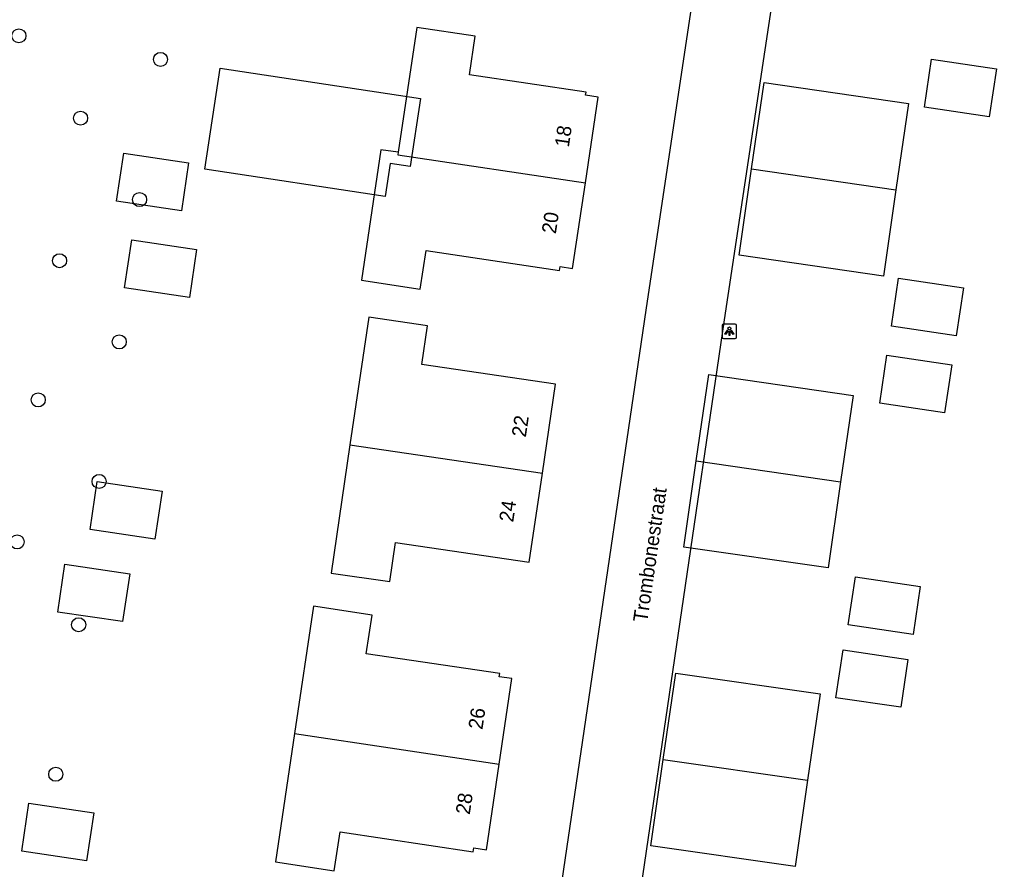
# Model space of a CAD drawing. Extents: x 164150 to 165261, y 382513 to 383432.
# Drawn here: x 164601.9 to 164669.9, y 382912.1 to 382971.2 of the extents above; entities that cross this region are included whole.
import ezdxf

# ---------------------------------------------------------------- set-up
doc = ezdxf.new("R2010")
doc.units = 0
for name, color, linetype in [('IMGEO_Boom', 7, 'Continuous'), ('IMGEO_Lichtpunt', 7, 'Continuous'), ('IMGEO_Openbare_ruimte_label', 7, 'Continuous'), ('IMGEO_Pand', 7, 'Continuous'), ('IMGEO_Pand_nummerreeks', 7, 'Continuous'), ('IMGEO_Pand_vergunning_verleend', 7, 'Continuous'), ('IMGEO_Rijbaan_lokaal_gesloten', 7, 'Continuous')]:
    doc.layers.add(name, color=color, linetype=linetype)

msp = doc.modelspace()

# ---------------------------------------------------------------- linework, layer by layer
at = {"layer": 'IMGEO_Boom'}
for centre in [(164601.874, 382970.068), (164611.726, 382968.429), (164606.168, 382964.34), (164610.269, 382958.67), (164604.702, 382954.42), (164608.857, 382948.767), (164603.219, 382944.734), (164607.456, 382939.06), (164601.753, 382934.851), (164606.031, 382929.089), (164604.437, 382918.68)]:
    msp.add_circle(centre, 0.489, dxfattribs=at)
at = {"layer": 'IMGEO_Lichtpunt'}
for p, q in [((164650.795, 382949.911), (164650.795, 382949.104)), ((164650.795, 382949.911), (164650.795, 382949.104)), ((164651.697, 382950.006), (164650.889, 382950.006)), ((164651.697, 382950.006), (164650.889, 382950.006)), ((164651.791, 382949.104), (164651.791, 382949.911)), ((164651.791, 382949.104), (164651.791, 382949.911)), ((164650.889, 382949.01), (164651.697, 382949.01)), ((164650.889, 382949.01), (164651.697, 382949.01))]:
    msp.add_line(p, q, dxfattribs=at)
for points in [[(164651.169, 382949.575), (164651.208, 382949.547), (164651.02, 382949.285), (164650.982, 382949.312), (164651.169, 382949.575)], [(164651.271, 382949.527), (164651.318, 382949.527), (164651.318, 382949.205), (164651.271, 382949.205), (164651.271, 382949.527)], [(164651.381, 382949.547), (164651.419, 382949.574), (164651.606, 382949.312), (164651.567, 382949.284), (164651.381, 382949.547)]]:
    msp.add_lwpolyline(points, dxfattribs=at)
msp.add_circle((164651.294, 382949.709), 0.0994, dxfattribs=at)
for centre, start, end in [((164650.889, 382949.911), 90, 180), ((164650.889, 382949.911), 90, 180), ((164651.697, 382949.911), 0, 90), ((164651.697, 382949.911), 0, 90), ((164650.889, 382949.104), 180, 270), ((164650.889, 382949.104), 180, 270), ((164651.697, 382949.104), 270, 0), ((164651.697, 382949.104), 270, 360)]:
    msp.add_arc(centre, 0.0946, start, end, dxfattribs=at)
at = {"layer": 'IMGEO_Pand'}
for points in [[(164641.274, 382959.842), (164642.165, 382965.796), (164641.296, 382965.936), (164641.329, 382966.158), (164633.225, 382967.358), (164633.618, 382970.037), (164629.544, 382970.648), (164628.257, 382961.966)], [(164628.257, 382961.966), (164627.059, 382962.137), (164625.707, 382953.056), (164629.782, 382952.439), (164630.197, 382955.128), (164639.476, 382953.749), (164639.517, 382954.02), (164640.383, 382953.888), (164641.274, 382959.842)], [(164628.257, 382961.966), (164628.231, 382961.794), (164641.274, 382959.842)], [(164638.283, 382939.627), (164639.2, 382945.819), (164629.894, 382947.194), (164630.295, 382949.896), (164626.21, 382950.499), (164624.901, 382941.609)], [(164624.901, 382941.609), (164623.587, 382932.686), (164627.671, 382932.096), (164628.073, 382934.816), (164637.365, 382933.434), (164638.283, 382939.627)], [(164624.901, 382941.609), (164638.283, 382939.627)], [(164635.278, 382919.39), (164636.165, 382925.354), (164635.291, 382925.472), (164635.325, 382925.697), (164626.04, 382927.072), (164626.44, 382929.762), (164622.359, 382930.374), (164621.048, 382921.507)], [(164621.048, 382921.507), (164619.728, 382912.58), (164623.802, 382911.962), (164624.213, 382914.665), (164633.479, 382913.287), (164633.522, 382913.555), (164634.39, 382913.426), (164635.278, 382919.39)], [(164621.048, 382921.507), (164635.278, 382919.39)]]:
    msp.add_lwpolyline(points, dxfattribs=at)
at = {"layer": 'IMGEO_Pand_vergunning_verleend'}
for points in [[(164664.866, 382965.103), (164665.362, 382968.439), (164669.869, 382967.768), (164669.372, 382964.433), (164664.866, 382965.103)], [(164614.808, 382960.791), (164615.871, 382967.816), (164629.805, 382965.709), (164629.089, 382960.974), (164627.689, 382961.186), (164627.342, 382958.895), (164614.808, 382960.791)], [(164652.839, 382960.806), (164653.707, 382966.813), (164663.749, 382965.362), (164662.881, 382959.355)], [(164608.669, 382958.564), (164609.166, 382961.9), (164613.672, 382961.229), (164613.175, 382957.894), (164608.669, 382958.564)], [(164662.881, 382959.355), (164662.013, 382953.348), (164651.972, 382954.799), (164652.839, 382960.806)], [(164652.839, 382960.806), (164662.881, 382959.355)], [(164609.226, 382952.532), (164609.722, 382955.867), (164614.228, 382955.197), (164613.732, 382951.861), (164609.226, 382952.532)], [(164662.568, 382949.872), (164663.064, 382953.207), (164667.57, 382952.536), (164667.074, 382949.201), (164662.568, 382949.872)], [(164661.754, 382944.507), (164662.25, 382947.842), (164666.756, 382947.172), (164666.26, 382943.836), (164661.754, 382944.507)], [(164648.984, 382940.493), (164649.852, 382946.5), (164659.894, 382945.049), (164659.026, 382939.042)], [(164659.026, 382939.042), (164658.158, 382933.035), (164648.116, 382934.486), (164648.984, 382940.493)], [(164648.984, 382940.493), (164659.026, 382939.042)], [(164606.832, 382935.72), (164607.328, 382939.055), (164611.834, 382938.384), (164611.338, 382935.049), (164606.832, 382935.72)], [(164604.581, 382929.972), (164605.078, 382933.307), (164609.584, 382932.636), (164609.087, 382929.301), (164604.581, 382929.972)], [(164659.563, 382929.087), (164660.059, 382932.422), (164664.566, 382931.751), (164664.069, 382928.416), (164659.563, 382929.087)], [(164658.701, 382924.009), (164659.198, 382927.345), (164663.704, 382926.674), (164663.207, 382923.339), (164658.701, 382924.009)], [(164646.695, 382919.714), (164647.563, 382925.721), (164657.604, 382924.27), (164656.736, 382918.263)], [(164656.736, 382918.263), (164655.869, 382912.256), (164645.827, 382913.707), (164646.695, 382919.714)], [(164646.695, 382919.714), (164656.736, 382918.263)], [(164602.079, 382913.324), (164602.576, 382916.659), (164607.082, 382915.988), (164606.586, 382912.653), (164602.079, 382913.324)]]:
    msp.add_lwpolyline(points, dxfattribs=at)
at = {"layer": 'IMGEO_Rijbaan_lokaal_gesloten'}
for points in [[(164631.941, 382858.849), (164645.496, 382950.967), (164651.008, 382987.673), (164651.902, 382993.63), (164653.078, 383001.462)], [(164658.504, 383000.69), (164650.933, 382950.305), (164641.67, 382887.255), (164640.801, 382881.34), (164637.731, 382860.442), (164636.909, 382854.849), (164636.824, 382854.453), (164636.636, 382853.576)]]:
    msp.add_lwpolyline(points, dxfattribs=at)

# ---------------------------------------------------------------- texts
at = {"layer": 'IMGEO_Openbare_ruimte_label'}
msp.add_text('Trombonestraat', height=1, rotation=81.65913, dxfattribs=at).set_placement((164645.573, 382929.212))
at = {"layer": 'IMGEO_Pand_nummerreeks'}
for s, rotation, p in [('18', 81.49179, (164640.122, 382962.278)), ('20', 81.49179, (164639.22, 382956.254)), ('22', 81.572, (164637.132, 382942.098)), ('24', 81.572, (164636.256, 382936.187)), ('26', 81.53762, (164634.113, 382921.752)), ('28', 81.53762, (164633.232, 382915.836))]:
    msp.add_text(s, height=1, rotation=rotation, dxfattribs=at).set_placement(p)

doc.saveas('drawing.dxf')
